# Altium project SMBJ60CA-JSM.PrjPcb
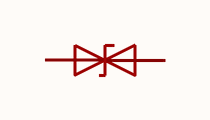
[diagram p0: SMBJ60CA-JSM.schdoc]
1 sheet, 1 parts. Net scope: global (net labels, ports and power ports of the same name join across sheets).

## Sheet SMBJ60CA-JSM.schdoc
size 127 x 101 mm

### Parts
D?  smbj60ca-jsm  [SMB_L4.6-W3.6-LS5.3-BI]  (value not drawn)

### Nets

Not connected (* = marked no-connect by the designer): D? 1 2

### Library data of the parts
D? = smbj60ca-jsm: 极性:双向;反向截止电压(Vrwm):60V;钳位电压:96.8V;峰值脉冲电流(Ipp):65.2A;峰值脉冲功率(Ppp):600W;击穿电压(VBR):73.7V;; Manufacturer: JSMSEMI(杰盛微); AddInBom: yes; ModelId: 07b8d28694b84373acb83e050c4644c9; ModelTransform: 212.598,141.732,0,0,0,0,0,0,0; Polarity: 双向; Reverse Stand-Off Voltage (Vrwm): 60V; Clamping Voltage: 96.8V; Peak Pulse Current (Ipp): 65.2A; Peak Pulse Power Dissipation (Ppp): 600W; Voltage - Breakdown: 73.7V; Reverse Leakage Current (Ir): 1uA; Number of Channels: 单路; Type: TVS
